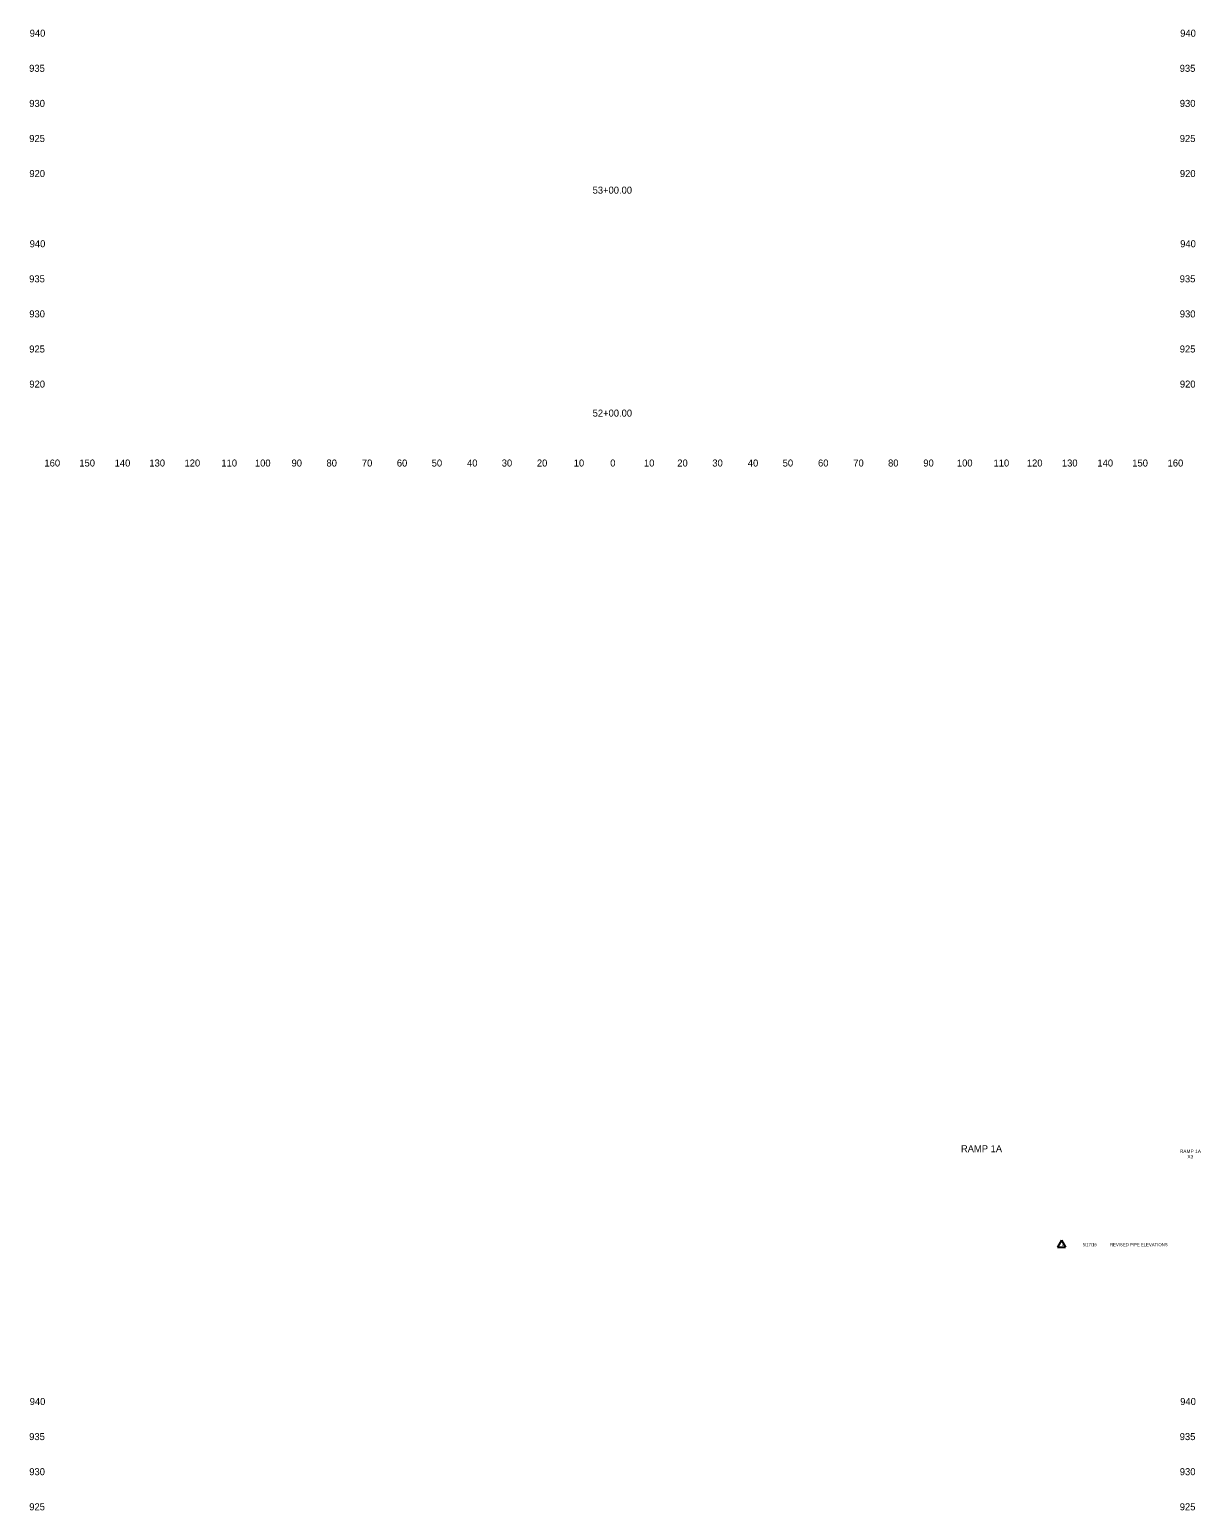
# Model space of a CAD drawing. Extents: x 4994 to 6873, y 4997 to 8804.
# Drawn here: x 4993.9 to 5327.4, y 5900 to 6322 of the extents above; entities that cross this region are included whole.
import ezdxf

# ---------------------------------------------------------------- set-up
doc = ezdxf.new("R2010")
doc.units = 0
for name, color, linetype in [('RD_SHT_ID', 7, 'Continuous'), ('RD_SHT_TX', 7, 'Continuous'), ('RD_XS_TX_Offset', 7, 'Continuous'), ('RD_XS_TX_Station', 7, 'Continuous')]:
    doc.layers.add(name, color=color, linetype=linetype)

msp = doc.modelspace()

# ---------------------------------------------------------------- linework, layer by layer
at = {"layer": 'RD_SHT_TX'}
for p, q in [((5287.89, 5977.01), (5286.75, 5974.98)), ((5287.89, 5977.01), (5289.03, 5974.98)), ((5286.75, 5974.98), (5289.03, 5974.98))]:
    msp.add_line(p, q, dxfattribs=at)

# ---------------------------------------------------------------- texts
at = {"layer": 'RD_SHT_ID'}
for s, height, p in [('RAMP 1A', 2, (5259.21, 6002.06)), ('RAMP 1A', 1, (5321.57, 6001.8)), ('X3', 1, (5323.74, 6000.3))]:
    msp.add_text(s, height=height, dxfattribs=at).set_placement(p)
at = {"layer": 'RD_SHT_TX'}
for s, p in [('1', (5287.89, 5975.31)), ('5/17/16', (5293.88, 5975.27)), ('REVISED PIPE ELEVATIONS', (5301.71, 5975.27))]:
    msp.add_text(s, height=0.88, dxfattribs=at).set_placement(p)
at = {"layer": 'RD_XS_TX_Offset'}
for s, p in [('940', (4993.89, 6320)), ('940', (5321.69, 6320)), ('935', (4993.75, 6310)), ('935', (5321.55, 6310)), ('930', (4993.78, 6300)), ('930', (5321.58, 6300)), ('925', (4993.77, 6290)), ('925', (5321.57, 6290)), ('920', (4993.8, 6280)), ('920', (5321.6, 6280)), ('940', (4993.89, 6260)), ('940', (5321.69, 6260)), ('935', (4993.75, 6250)), ('935', (5321.55, 6250)), ('930', (4993.78, 6240)), ('930', (5321.58, 6240)), ('925', (4993.77, 6230)), ('925', (5321.57, 6230)), ('920', (4993.8, 6220)), ('920', (5321.6, 6220)), ('160', (4998.1, 6197.5)), ('150', (5008.04, 6197.5)), ('140', (5018.1, 6197.5)), ('130', (5027.99, 6197.5)), ('120', (5038.01, 6197.5)), ('110', (5048.51, 6197.5)), ('100', (5058.07, 6197.5)), ('90', (5068.5, 6197.5)), ('80', (5078.46, 6197.5)), ('70', (5088.54, 6197.5)), ('60', (5098.5, 6197.5)), ('50', (5108.43, 6197.5)), ('40', (5118.5, 6197.5)), ('30', (5128.39, 6197.5)), ('20', (5138.4, 6197.5)), ('10', (5148.91, 6197.5)), ('0', (5159.3, 6197.5)), ('0', (5159.3, 6197.5)), ('10', (5168.91, 6197.5)), ('20', (5178.4, 6197.5)), ('30', (5188.39, 6197.5)), ('40', (5198.5, 6197.5)), ('50', (5208.43, 6197.5)), ('60', (5218.5, 6197.5)), ('70', (5228.54, 6197.5)), ('80', (5238.46, 6197.5)), ('90', (5248.5, 6197.5)), ('100', (5258.07, 6197.5)), ('110', (5268.51, 6197.5)), ('120', (5278.01, 6197.5)), ('130', (5287.99, 6197.5)), ('140', (5298.1, 6197.5)), ('150', (5308.04, 6197.5)), ('160', (5318.1, 6197.5)), ('940', (4993.89, 5930)), ('940', (5321.69, 5930)), ('935', (4993.75, 5920)), ('935', (5321.55, 5920)), ('930', (4993.78, 5910)), ('930', (5321.58, 5910)), ('925', (4993.77, 5900)), ('925', (5321.57, 5900))]:
    msp.add_text(s, height=2, dxfattribs=at).set_placement(p)
at = {"layer": 'RD_XS_TX_Station'}
for s, p in [('53+00.00', (5154.28, 6275.28)), ('52+00.00', (5154.29, 6211.73))]:
    msp.add_text(s, height=2, dxfattribs=at).set_placement(p)

doc.saveas('drawing.dxf')
